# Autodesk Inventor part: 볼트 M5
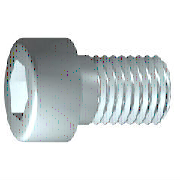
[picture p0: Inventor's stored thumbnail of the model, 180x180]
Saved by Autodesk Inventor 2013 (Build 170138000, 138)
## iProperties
IsCustomPart: 0
Created: 2015-11
Part Number: 볼트 M5
Material: 스테인리스강
Description: 6각머리 태핑 나사
Document SubType Name: Modeling
Standard: KS B 1003
Designer: mdu
Standards Organization: KS
Language: ko-KR
Size Designation: M 5 x 20
Categories: <MemberInstance><Categories><Category DisplayName="조임쇠" InternalName="e4da775c-781d-43d5-af7c-5136215cf5a6" Mnemonic="FSTN"><Category DisplayName="볼트" InternalN
Density: 8.08 g/cm^3
Mass: 5.10181 g
Surface Area: 5.88237 cm^2
Volume: 0.631412 cm^3
Author: mdu
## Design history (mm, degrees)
sketch "스케치1"
  geometry: L1 (-1.167, 0)-(20, 0); L2 (20, 0)-(20, 2.5); L3 (20, 2.5)-(2, 2.5); L4 (2, 2.5)-(1.509, 2.5); L5 (1.509, 2.5)-(0, 2.5); L6 (0, 2.5)-(0, 4.25); L7 (0, 4.25)-(-5, 4.25); L8 (-5, 4.25)-(-5, 2.309); L9 (-5, 2.309)-(-2.5, 2.309); L10 (-2.5, 2.309)-(-1.167, 0); L11 (-10, 0)-(25, 0) reference; L12 (0, -0.85)-(0, 5.1) reference; L13 (2, 2.5)-(0, 2.5)
  constraints: 22 end point, 6 parallel, 2 collinear, 2 perpendicular, 1 horizontal, 1 point on line
  dimensions: "d1" = 18 distance from line of L3.end L2 (= GEL); "d2" = 0.49086 distance of L4.end L3.end (computed from GAL); "d3" = 5 distance between parallel lines of L8 L6 (= KOH); "d4" = 2.5 distance of L8.end L9.end (= INTI); "d5" = 60 deg angle of L10 L1; "d6" = 5 diameter of L3 L1 (= GD); "d7" = 5 diameter of L5 L1 (= BDM); "d8" = 4.6188 diameter of L9 L1 (= 1.1547 x SW); "d9" = 8.5 diameter of L7 L1 (= KOD); "d26" = 20 distance between parallel lines of L12 L2 (= NLG)
revolve "본체" sketch "스케치1" stored, may be unused: angle "d10" = 90 deg
sketch "스케치2"
  geometry: L1 (0, -5.95)-(0, 5.95) reference; L2 (-5.95, 0)-(5.95, 0) reference; L3 (2.309, 0)-(1.155, -2); L4 (1.155, -2)-(-1.155, -2); L5 (-1.155, -2)-(-2.309, 0); L6 (-2.309, 0)-(-1.155, 2); L7 (-1.155, 2)-(1.155, 2); L8 (1.155, 2)-(2.309, 0); 2 further points
  constraints: 12 end point, 1 coincident, 1 horizontal alignment, 1 point on line, 12 other
extrude "슬롯" join sketch "스케치2" stored distance "d11" = 10; taper "d12" = 0 deg
workplane "Work Plane1"
fillet "Fillet2" dims "d30" = 0.1 (= R)
body "Solid1"
fillet "모깎기1" dims "d17" = 0.5 (= RR)
feature "스레드" dims "d13" = 18 (= GEL), "d14" = 0
chamfer "모따기1" distance "d15" = 0.49076 (= -0.5 x SPD + 0.5 x GD); stored, may be unused: second distance "d16" = 0.49076 (= GUL), angle "d27" = 45 deg
other parameters: "GD" = 5 (= NND) [user parameter; used in 2 equation terms], "NLG" = 20 [user parameter; used in 1 equation term], "GEL" = 18 [user parameter; used in 2 equation terms], "KOD" = 8.5 [user parameter; used in 1 equation term], "KOH" = 5 [user parameter; used in 1 equation term], "INTI" = 2.5 [user parameter; used in 1 equation term], "GAL" = 0.49076 (= 0.61345 x PTC) [user parameter; used in 1 equation term], "GUL" = 0.49076 (= 0.61345 x PTC) [user parameter; used in 1 equation term], "BDM" = 5 (= NND) [user parameter; used in 1 equation term], "SW" = 4 [user parameter; used in 2 equation terms], "RR" = 0.5 [user parameter; used in 1 equation term], "SPD" = 4.01848 (= NND - 1.2269 x PTC) [user parameter; used in 1 equation term], "d19" = 0, "d28" = 0, "d29" = 0, "R" = 0.1 [user parameter; used in 1 equation term], "PHH" = 0.2 [user parameter], "GD1" = 4.01848 (= THREADDIA - 1.2269 x PTC) [user parameter], "THREADDIA" = 5 [user parameter; used in 1 equation term], "FAWI" = 45 deg [user parameter], "TPU" = 12.5 (computed from PTC) [user parameter], "PTC" = 0.8 [user parameter; used in 5 equation terms], "NND" = 5 [user parameter; used in 3 equation terms], "TOA" = 30 deg [user parameter], "E0" = 4.62 (= 1.155 x SW) [user parameter]
